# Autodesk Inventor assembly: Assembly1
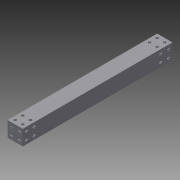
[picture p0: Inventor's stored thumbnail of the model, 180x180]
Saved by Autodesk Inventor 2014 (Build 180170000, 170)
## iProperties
Created: 2014-06
Part Number: Assembly1
Document SubType Name: Assembly
Designer: Aser
Author: Aser
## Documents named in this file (4)
- C:\Users\Aser\Documents\Assembly1.iam
- C:\Users\Aser\Documents\Side1.ipt
- C:\Users\Aser\Documents\Side2.ipt
- C:\Users\Aser\Documents\Side3.ipt
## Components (6 placed, 3 different names)
1. Side1:1 — Flush:1, Flush:2, Flush:3, Flush:4, Flush:5, Flush:8, Flush:9, Flush:11, Flush:13
2. Side1:2 — Flush:1, Flush:2, Flush:6, Flush:10
3. Side2:1 — Flush:3, Flush:4, Flush:5, Flush:6, Flush:7, Flush:12, Flush:14, Flush:15
4. Side2:2 — Flush:7, Flush:8, Flush:9
5. Side3:1 — Flush:10, Flush:11, Flush:12
6. Side3:2 — Flush:13, Flush:14, Flush:15
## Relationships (15: Flush 15)
- Flush:1: Side1:1 ↔ Side1:2
- Flush:2: Side1:1 ↔ Side1:2
- Flush:3: Side1:1 ↔ Side2:1
- Flush:4: Side1:1 ↔ Side2:1
- Flush:5: Side1:1 ↔ Side2:1
- Flush:6: Side1:2 ↔ Side2:1
- Flush:7: Side2:1 ↔ Side2:2
- Flush:8: Side1:1 ↔ Side2:2
- Flush:9: Side1:1 ↔ Side2:2
- Flush:10: Side1:2 ↔ Side3:1
- Flush:11: Side1:1 ↔ Side3:1
- Flush:12: Side2:1 ↔ Side3:1
- Flush:13: Side1:1 ↔ Side3:2
- Flush:14: Side2:1 ↔ Side3:2
- Flush:15: Side2:1 ↔ Side3:2
